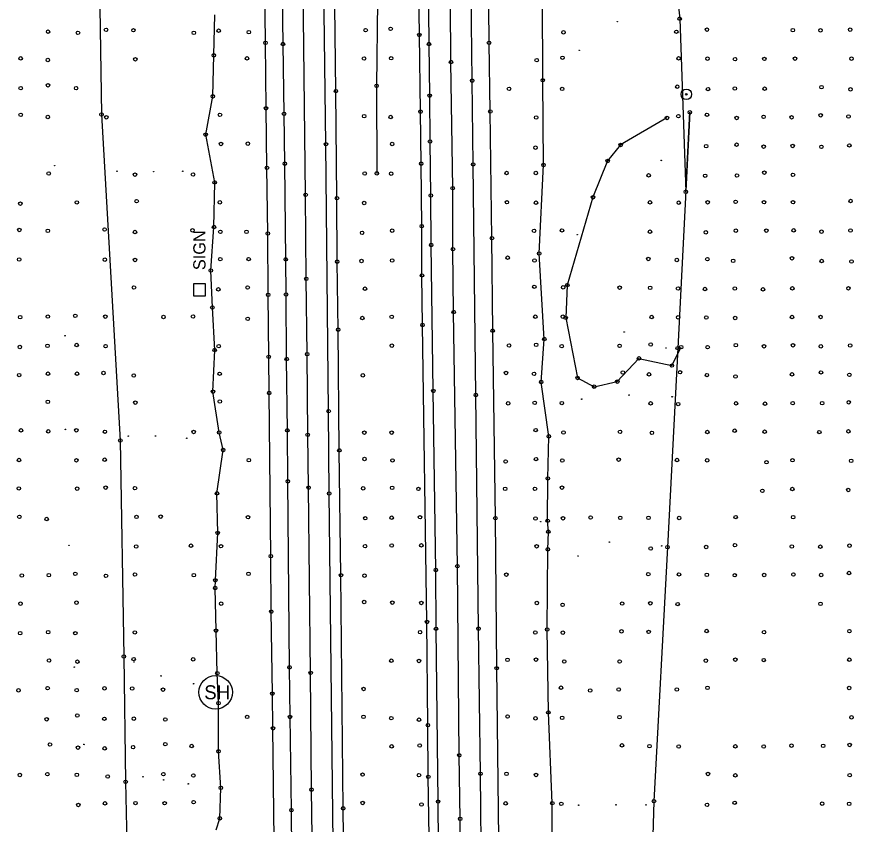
# Model space of a CAD drawing. Extents: x 20503438 to 20508873, y 7964251 to 7984667.
# Drawn here: x 20505218.6 to 20505698, y 7982806.9 to 7983269.7 of the extents above; entities that cross this region are included whole.
import ezdxf

# ---------------------------------------------------------------- set-up
doc = ezdxf.new("R2010")
doc.units = 0
for name, color, linetype in [('SurBreakLine', 7, 'Continuous'), ('SurControl', 7, 'Continuous'), ('SurDrainageArrowDown', 7, 'Continuous'), ('SurDrainageArrowUp', 7, 'Continuous'), ('SurEdgeRoadPaved', 7, 'Continuous'), ('SurEdgeShoulderPaved', 7, 'Continuous'), ('SurFenceWire', 7, 'Continuous'), ('SurNaturalCells', 7, 'Continuous'), ('SurPointsNonDTM', 7, 'Continuous'), ('SurRoadPoints', 7, 'Continuous'), ('SurSurveyPoints', 7, 'Continuous'), ('SurTreeLineRight', 7, 'Continuous')]:
    doc.layers.add(name, color=color, linetype=linetype)

msp = doc.modelspace()

# ---------------------------------------------------------------- linework, layer by layer
at = {"layer": 'SurBreakLine'}
for points in [[(20505388.09, 7982786.72), (20505387.46, 7982826.69), (20505386.97, 7982893.61), (20505385.8, 7982999.79), (20505385.32, 7983030.07), (20505384.98, 7983076.27), (20505384.47, 7983119.49), (20505384.1, 7983167.57), (20505382.15, 7983337.32), (20505379.76, 7983573.99), (20505379.24, 7983609.63), (20505378.24, 7983709.76), (20505377.29, 7983778.59), (20505376.87, 7983823.71), (20505376.2, 7983914.92), (20505375.66, 7983955.45), (20505374.47, 7984054.03), (20505371.04, 7984409.5), (20505370.34, 7984465.16)], [(20505472.94, 7982774.42), (20505472.68, 7982809.97), (20505472.15, 7982846.38), (20505471.07, 7982954.8), (20505468.94, 7983100.42), (20505468.55, 7983136.44), (20505468.38, 7983171.42), (20505467.38, 7983243.73), (20505467.16, 7983277.76), (20505466.96, 7983298.39), (20505466.31, 7983351.76), (20505465.95, 7983385.57), (20505465.78, 7983423.2), (20505464.95, 7983485.18), (20505463.87, 7983574.98), (20505462.87, 7983680.32), (20505462, 7983754.37)]]:
    msp.add_lwpolyline(points, dxfattribs=at)
at = {"layer": 'SurControl'}
for centre in [(20505562.72, 7983266.82), (20505540.92, 7983250.41), (20505587.88, 7983187.29), (20505240.3, 7983184.28), (20505275.98, 7983181.13), (20505297.02, 7983180.89), (20505313.71, 7983181.13), (20505539.78, 7983144.77), (20505246.26, 7983086.81), (20505566.66, 7983089.01), (20505590.66, 7983079.85), (20505542.35, 7983050.5), (20505569.5, 7983052.8), (20505594.17, 7983051.87), (20505246.45, 7983033.15), (20505282.48, 7983029.34), (20505298.08, 7983029.41), (20505315.98, 7983028.13), (20505518.87, 7982980.3), (20505248.53, 7982966.75), (20505558.2, 7982968.59), (20505588.18, 7982966.41), (20505540.27, 7982960.65), (20505285.75, 7982899.87), (20505251.54, 7982896.94), (20505301.31, 7982891.9), (20505319.88, 7982887.38), (20505257.06, 7982852.63), (20505290.94, 7982834.09), (20505302.75, 7982832.29), (20505316.82, 7982830.05), (20505540.57, 7982817.81), (20505562.01, 7982818), (20505579.21, 7982817.97)]:
    msp.add_circle(centre, 0.15, dxfattribs=at)
at = {"layer": 'SurDrainageArrowDown'}
msp.add_lwpolyline([(20505332.76, 7982803.76), (20505334.91, 7982810.26), (20505335.55, 7982827.71), (20505334.17, 7982848.71), (20505334.18, 7982876.28), (20505333.51, 7982893.44), (20505332.77, 7982917.85), (20505332.28, 7982942.23), (20505332.37, 7982946.68), (20505333.74, 7982973.81), (20505333.28, 7982996.49), (20505336.88, 7983021.4), (20505334.57, 7983031.42), (20505331, 7983054.83), (20505332.02, 7983078.67), (20505330.68, 7983103.07), (20505329.78, 7983124.21), (20505331.56, 7983149.14), (20505332.02, 7983174.71), (20505326.84, 7983202.11), (20505330.95, 7983224.07), (20505331.52, 7983247.58), (20505332.03, 7983270.82)], dxfattribs=at)
at = {"layer": 'SurDrainageArrowUp'}
for points in [[(20505435.69, 7983412.57), (20505432.5, 7983412.27), (20505429.44, 7983411.43), (20505426.11, 7983408.1), (20505425.72, 7983400.28), (20505426.05, 7983374.69), (20505426.24, 7983351.03), (20505426.02, 7983326.08), (20505425.25, 7983278.5), (20505424.77, 7983230.05), (20505424.95, 7983179.92)], [(20505525.47, 7982791.21), (20505525.48, 7982818.97), (20505523.24, 7982870.97), (20505522.53, 7982918.48), (20505522.94, 7982964.39), (20505523.24, 7982974.53), (20505522.79, 7982980.81), (20505522.94, 7983005.08), (20505523.5, 7983029.16), (20505519.1, 7983060.32), (20505520.91, 7983084.94), (20505517.95, 7983133.99), (20505520.47, 7983184.73), (20505520.01, 7983233.27), (20505519.87, 7983280.64)]]:
    msp.add_lwpolyline(points, dxfattribs=at)
at = {"layer": 'SurEdgeRoadPaved'}
for points in [[(20505399.87, 7982796.43), (20505397.64, 7982996.42), (20505397.31, 7983043.62), (20505395.75, 7983196.59), (20505394.62, 7983287.56), (20505393.71, 7983393.22), (20505391.47, 7983583.96), (20505391.16, 7983613.2), (20505390.95, 7983649.19), (20505388.69, 7983846.62), (20505387.86, 7983937.63), (20505387.13, 7984000.04), (20505387.09, 7984002.85), (20505386.65, 7984030.88), (20505382.6, 7984465.04)], [(20505484.93, 7982775.73), (20505484.31, 7982835.82), (20505483.21, 7982919), (20505481.67, 7983052.88), (20505480.16, 7983185.03), (20505479.57, 7983233.06), (20505478.99, 7983282.65), (20505478.07, 7983364.47), (20505477.49, 7983427.45), (20505476.34, 7983527.07), (20505475.78, 7983595.33), (20505474.69, 7983687.27), (20505474.16, 7983745.86), (20505473.26, 7983818.48), (20505472.69, 7983886.02), (20505472.06, 7983927.63), (20505471.61, 7983985.32), (20505470.9, 7984047.39), (20505470.84, 7984053.12), (20505468.38, 7984286.35), (20505467.61, 7984344.39), (20505467.44, 7984376.12), (20505466.29, 7984465.77)], [(20505376.87, 7982720.03), (20505375.97, 7982814.93), (20505375.18, 7982868.35), (20505374.84, 7982896.8), (20505373.9, 7983003.41), (20505373.63, 7983032.61), (20505373.23, 7983073.5), (20505372.9, 7983110.52), (20505372.72, 7983130.62), (20505372.2, 7983185.46), (20505371.76, 7983214.03), (20505371.18, 7983254.01), (20505370.55, 7983308.55), (20505370.11, 7983376.99), (20505368.96, 7983469.33), (20505368.55, 7983508.46), (20505368.26, 7983546.26), (20505367.99, 7983574.82), (20505367.67, 7983598.7), (20505367.02, 7983649.08), (20505365.92, 7983751.56)], [(20505460.57, 7982745.92), (20505460.02, 7982819.87), (20505458.85, 7982918.92), (20505458.72, 7982952.55), (20505457.28, 7983055.18), (20505456.07, 7983138.84), (20505455.85, 7983167.22), (20505455.42, 7983198.13), (20505455.22, 7983224.45), (20505454.85, 7983254.02), (20505454.55, 7983292.83), (20505453.72, 7983358.98), (20505453.59, 7983387.67), (20505452.51, 7983492.09), (20505451.03, 7983612.62), (20505450.51, 7983669.13), (20505449.78, 7983725.38), (20505449.64, 7983752.99)]]:
    msp.add_lwpolyline(points, dxfattribs=at)
at = {"layer": 'SurEdgeShoulderPaved'}
for points in [[(20505495.09, 7982782.36), (20505493.62, 7982896.29), (20505492.84, 7982982.27), (20505491.34, 7983089.74), (20505490.88, 7983142.78), (20505489.93, 7983215.38), (20505489.23, 7983254.71), (20505488.8, 7983316.65), (20505488.28, 7983347.9), (20505487.72, 7983412.22), (20505487.68, 7983415.04), (20505486.79, 7983497.7), (20505486.21, 7983568.02), (20505484.96, 7983655.65), (20505482.47, 7983897.96)], [(20505406.44, 7982753), (20505405.66, 7982815.99), (20505404.36, 7982949.58), (20505403.42, 7983021.17), (20505402.75, 7983090.32), (20505402.21, 7983129.29), (20505402.08, 7983165.66), (20505401.47, 7983227.06), (20505400.04, 7983341.4), (20505399.38, 7983413.75), (20505397.66, 7983569.46), (20505397.07, 7983624.87), (20505396.26, 7983698.73), (20505395.49, 7983760.73)], [(20505366.98, 7982718.13), (20505365.41, 7982861.87), (20505365.07, 7982881.72), (20505364.41, 7982928.72), (20505364.19, 7982960.53), (20505363.22, 7983054.03), (20505362.96, 7983074.76), (20505362.61, 7983110.31), (20505362.42, 7983145.46), (20505361.97, 7983183.06), (20505361.41, 7983217.22), (20505361.15, 7983254.72), (20505360.71, 7983288.06), (20505360.6, 7983299.77), (20505360.47, 7983317.66), (20505360.11, 7983363.4), (20505359.23, 7983433.57), (20505358.71, 7983478.18), (20505357.37, 7983616.7), (20505356.33, 7983687.67), (20505355.63, 7983757.41)], [(20505454.87, 7982799.91), (20505454.43, 7982834.05), (20505454.19, 7982863.65), (20505453.63, 7982922.83), (20505451.09, 7983092.97), (20505450.78, 7983121.42), (20505450.67, 7983149.63), (20505450.35, 7983185.44), (20505449.91, 7983215.31), (20505449.29, 7983259.23), (20505449.04, 7983285.01), (20505448.83, 7983321.6), (20505448.42, 7983357.03), (20505448.19, 7983377.57), (20505447.91, 7983416.56), (20505446.96, 7983486.61), (20505445.72, 7983599.24), (20505445.42, 7983622.54), (20505445.14, 7983645.21), (20505445.01, 7983677.11), (20505444.05, 7983741.95)]]:
    msp.add_lwpolyline(points, dxfattribs=at)
at = {"layer": 'SurFenceWire'}
for points in [[(20505559.43, 7984640.78), (20505560.17, 7984588.37), (20505562.54, 7984378.42), (20505563.28, 7984280.23), (20505565.01, 7984077.63), (20505567.76, 7983869.69), (20505568.29, 7983819.98), (20505570.2, 7983612.37), (20505577.97, 7983452.36), (20505588.36, 7983359.69), (20505598.48, 7983268.53), (20505602.02, 7983169.29), (20505604.28, 7983214.9), (20505597.36, 7983079.77), (20505591.48, 7982965.7), (20505583.74, 7982820.12), (20505580.19, 7982701.02)], [(20505263.07, 7983570.84), (20505264.2, 7983465.89), (20505264.6, 7983384.22), (20505265.76, 7983299.57), (20505267.13, 7983213.61), (20505277.91, 7983026.79), (20505279.9, 7982903.03), (20505280.94, 7982831.19), (20505284.45, 7982664.16), (20505302.4, 7982645.24), (20505317.11, 7982628.42), (20505340.63, 7982610.34)]]:
    msp.add_lwpolyline(points, dxfattribs=at)
at = {"layer": 'SurNaturalCells'}
msp.add_circle((20505332.54, 7982882.51), 9.59, dxfattribs=at)
at = {"layer": 'SurPointsNonDTM'}
for centre in [(20505598.48, 7983268.53), (20505267.13, 7983213.61), (20505591.19, 7983211.65), (20505604.28, 7983214.9), (20505564.63, 7983196.17), (20505557.18, 7983187.03), (20505602.02, 7983169.29), (20505548.76, 7983166.18), (20505534.06, 7983115.88), (20505533.17, 7983097.07), (20505597.36, 7983079.77), (20505599.33, 7983080.32), (20505575.13, 7983073.88), (20505594.02, 7983069.75), (20505539.96, 7983062.66), (20505549.45, 7983057.65), (20505562.73, 7983060.56), (20505277.91, 7983026.79), (20505591.48, 7982965.7), (20505279.9, 7982903.03), (20505280.94, 7982831.19), (20505583.74, 7982820.12)]:
    msp.add_circle(centre, 1, dxfattribs=at)
at = {"layer": 'SurRoadPoints'}
msp.add_lwpolyline([(20505326.66, 7983113.23), (20505326.66, 7983113.23), (20505326.66, 7983116.66), (20505319.8, 7983116.66), (20505319.8, 7983109.8), (20505326.66, 7983109.8), (20505326.66, 7983113.23)], dxfattribs=at)
for radius in [3, 0.5]:
    msp.add_circle((20505602.28, 7983225.21), radius, dxfattribs=at)
at = {"layer": 'SurSurveyPoints'}
for centre in [(20505236.52, 7983261.11), (20505253.65, 7983260.41), (20505269.75, 7983262.13), (20505285.42, 7983261.93), (20505320.03, 7983260.48), (20505334.27, 7983261.65), (20505351.53, 7983260.86), (20505418.48, 7983261.99), (20505432.81, 7983262.76), (20505449.29, 7983259.23), (20505531.93, 7983260.73), (20505596.56, 7983261.06), (20505614.08, 7983262.29), (20505663.32, 7983262.01), (20505679.16, 7983261.88), (20505696.22, 7983262.28), (20505361.15, 7983254.72), (20505371.18, 7983254.01), (20505454.85, 7983254.02), (20505489.23, 7983254.71), (20505220.82, 7983245.81), (20505236.4, 7983244.85), (20505286.54, 7983245.3), (20505331.52, 7983247.58), (20505350.47, 7983245.83), (20505417.57, 7983245.74), (20505433.15, 7983245.88), (20505516.53, 7983244.78), (20505531.29, 7983246.16), (20505597.86, 7983245.81), (20505614.4, 7983245.63), (20505630.19, 7983245.37), (20505647.01, 7983245.5), (20505664.53, 7983245.68), (20505696.96, 7983245.64), (20505467.38, 7983243.73), (20505236.49, 7983230.38), (20505424.77, 7983230.05), (20505479.57, 7983233.06), (20505520.01, 7983233.27), (20505597.08, 7983229.55), (20505220.85, 7983228.72), (20505252.57, 7983228.7), (20505401.47, 7983227.06), (20505500.68, 7983228.33), (20505531.14, 7983228.31), (20505614.72, 7983228.21), (20505630.12, 7983228.55), (20505647.17, 7983228.44), (20505679.77, 7983229.27), (20505696.37, 7983228.08), (20505330.95, 7983224.07), (20505455.22, 7983224.45), (20505361.41, 7983217.22), (20505449.91, 7983215.31), (20505489.93, 7983215.38), (20505220.82, 7983213.48), (20505236.35, 7983212.18), (20505269.9, 7983212.06), (20505335.01, 7983213.48), (20505371.76, 7983214.03), (20505417.67, 7983212.71), (20505432.87, 7983212.18), (20505516.21, 7983211.89), (20505597.71, 7983212.68), (20505614.12, 7983213.5), (20505631.1, 7983211.66), (20505646.56, 7983212.29), (20505662.61, 7983212.05), (20505679.32, 7983213.2), (20505695.23, 7983212.51), (20505326.84, 7983202.11), (20505335.62, 7983196.74), (20505351.03, 7983196.97), (20505395.75, 7983196.59), (20505433.74, 7983196.73), (20505455.42, 7983198.13), (20505631.09, 7983196.33), (20505695.73, 7983195.92), (20505515.85, 7983194.63), (20505613.64, 7983195.48), (20505646.58, 7983195.21), (20505663.24, 7983195.62), (20505679.71, 7983195.1), (20505361.97, 7983183.06), (20505372.2, 7983185.46), (20505450.35, 7983185.44), (20505480.16, 7983185.03), (20505520.47, 7983184.73), (20505236.86, 7983179.83), (20505286.37, 7983179.18), (20505319.57, 7983179.22), (20505417.96, 7983179.86), (20505424.95, 7983179.92), (20505433.17, 7983179.7), (20505499.28, 7983180.08), (20505516.06, 7983180.09), (20505580.7, 7983178.77), (20505613.09, 7983178.53), (20505631.3, 7983178.7), (20505647.03, 7983180.32), (20505663.38, 7983179.03), (20505332.02, 7983174.71), (20505384.1, 7983167.57), (20505455.85, 7983167.22), (20505468.38, 7983171.42), (20505220.63, 7983162.55), (20505253.01, 7983163.25), (20505287.28, 7983164), (20505334.96, 7983163.28), (20505402.08, 7983165.66), (20505417.69, 7983162.95), (20505499.47, 7983163.36), (20505516.14, 7983163.07), (20505581.48, 7983163.29), (20505597.95, 7983163.07), (20505614.5, 7983163.32), (20505630.54, 7983163.61), (20505646.84, 7983163.35), (20505663.44, 7983163.36), (20505696.42, 7983164.05), (20505331.56, 7983149.14), (20505450.67, 7983149.63), (20505220.03, 7983147.45), (20505236.39, 7983146.97), (20505268.92, 7983147.72), (20505286.35, 7983146.28), (20505319.25, 7983147.26), (20505335.24, 7983146.36), (20505350.26, 7983146.39), (20505362.42, 7983145.46), (20505416.47, 7983145.82), (20505433.69, 7983147.03), (20505515.03, 7983146.96), (20505531.01, 7983147.21), (20505581.5, 7983146.46), (20505613.49, 7983146.13), (20505630.67, 7983147.05), (20505648.12, 7983147.07), (20505663.84, 7983147.22), (20505679.72, 7983146.51), (20505696.34, 7983147.14), (20505456.07, 7983138.84), (20505490.88, 7983142.78), (20505468.55, 7983136.44), (20505517.95, 7983133.99), (20505219.92, 7983130.55), (20505269.03, 7983130.43), (20505286.29, 7983130.28), (20505335.2, 7983130.71), (20505351.43, 7983130.78), (20505372.72, 7983130.62), (20505402.21, 7983129.29), (20505416.11, 7983129.69), (20505433.67, 7983129.95), (20505499.86, 7983131.59), (20505515.31, 7983130), (20505580.47, 7983130.85), (20505596.82, 7983130.21), (20505614.34, 7983130.77), (20505629.11, 7983129.78), (20505662.85, 7983131.24), (20505679.83, 7983129.67), (20505696.94, 7983129.4), (20505329.78, 7983124.21), (20505384.47, 7983119.49), (20505450.78, 7983121.42), (20505285.73, 7983114.46), (20505350.86, 7983114.5), (20505515.17, 7983114.92), (20505531.74, 7983114.55), (20505564.07, 7983114.43), (20505334.11, 7983113.42), (20505362.61, 7983110.31), (20505372.9, 7983110.52), (20505418.14, 7983113.8), (20505581.55, 7983114.33), (20505597.54, 7983113.93), (20505613.02, 7983113.6), (20505630.09, 7983113.91), (20505646.25, 7983113.41), (20505663.08, 7983113.99), (20505695.18, 7983114.05), (20505330.68, 7983103.07), (20505468.94, 7983100.42), (20505220.52, 7983097.49), (20505236.35, 7983097.83), (20505252.13, 7983098.26), (20505269.31, 7983097.81), (20505302.66, 7983097.56), (20505319.57, 7983097.9), (20505350.94, 7983096.55), (20505416.65, 7983097), (20505433.46, 7983097.65), (20505515.75, 7983097.74), (20505531.49, 7983097.82), (20505582.43, 7983097.58), (20505597.59, 7983097.4), (20505613.71, 7983097.29), (20505630.28, 7983097.04), (20505662.82, 7983097.55), (20505679.23, 7983097.62), (20505451.09, 7983092.97), (20505402.75, 7983090.32), (20505491.34, 7983089.74), (20505236.16, 7983081.09), (20505252.93, 7983081.53), (20505269.47, 7983080.89), (20505334.3, 7983080.88), (20505433.52, 7983081.18), (20505500.67, 7983081.27), (20505516.27, 7983081.61), (20505520.91, 7983084.94), (20505530.89, 7983080.9), (20505564.03, 7983081.09), (20505581.89, 7983081.79), (20505630.63, 7983081.48), (20505663.45, 7983081.36), (20505696.15, 7983081.23), (20505220.3, 7983080.4), (20505332.02, 7983078.67), (20505384.98, 7983076.27), (20505614.5, 7983080.28), (20505646.78, 7983080.82), (20505679.36, 7983080.77), (20505362.96, 7983074.76), (20505373.23, 7983073.5), (20505219.94, 7983064.3), (20505236.51, 7983065.11), (20505253.05, 7983065.1), (20505268.26, 7983065.45), (20505285.61, 7983064.08), (20505334.84, 7983065.06), (20505416.86, 7983064.12), (20505498.9, 7983065.53), (20505515.02, 7983065.04), (20505565.92, 7983065.81), (20505580.88, 7983064.72), (20505598.71, 7983065.93), (20505614.08, 7983064.3), (20505630.48, 7983063.5), (20505662.84, 7983064.7), (20505679.43, 7983065.82), (20505695.71, 7983064.48), (20505519.1, 7983060.32), (20505331, 7983054.83), (20505363.22, 7983054.03), (20505457.28, 7983055.18), (20505481.67, 7983052.88), (20505236.41, 7983048.97), (20505286.52, 7983048.5), (20505334.95, 7983049.16), (20505500.18, 7983048.07), (20505515.4, 7983048.38), (20505530.97, 7983048.25), (20505581.83, 7983048.1), (20505597.62, 7983047.68), (20505630.81, 7983048.1), (20505647.36, 7983047.9), (20505663.24, 7983048.23), (20505680.1, 7983048.24), (20505695.37, 7983048.69), (20505397.31, 7983043.62), (20505220.99, 7983032.63), (20505236.61, 7983032.04), (20505252.69, 7983032.67), (20505269.08, 7983031.82), (20505319.95, 7983031.69), (20505334.57, 7983031.42), (20505373.63, 7983032.61), (20505385.32, 7983030.07), (20505417.8, 7983031.3), (20505433.45, 7983031.32), (20505515.95, 7983032.77), (20505523.5, 7983029.16), (20505531.87, 7983031.4), (20505564.28, 7983031.79), (20505582.56, 7983031.19), (20505614.37, 7983031.66), (20505630, 7983032.4), (20505647.15, 7983031.87), (20505678.51, 7983031.63), (20505695.18, 7983032.03), (20505336.88, 7983021.4), (20505403.42, 7983021.17), (20505219.84, 7983015.6), (20505252.76, 7983015.46), (20505268.95, 7983015.8), (20505351.59, 7983015.54), (20505417.88, 7983016.17), (20505433.89, 7983015.39), (20505498.71, 7983014.8), (20505516.18, 7983016.15), (20505531.2, 7983015.37), (20505563.48, 7983015.86), (20505596.94, 7983015.62), (20505614.25, 7983015.43), (20505648.27, 7983014.35), (20505663.13, 7983015.49), (20505696.73, 7983015.14), (20505522.94, 7983005.08), (20505269.56, 7982999.79), (20505286.3, 7982999.46), (20505373.9, 7983003.41), (20505385.8, 7982999.79), (20505433.68, 7982999.68), (20505531.04, 7982999.79), (20505219.75, 7982999.34), (20505253.22, 7982999.23), (20505333.28, 7982996.49), (20505397.64, 7982996.42), (20505417.08, 7982999.36), (20505448.75, 7982999.06), (20505498.5, 7982999.08), (20505515.53, 7982999.11), (20505645.87, 7982997.97), (20505663.06, 7982998.98), (20505695.08, 7982998.46), (20505220.05, 7982983.05), (20505235.74, 7982981.81), (20505287.19, 7982983.01), (20505301.04, 7982983.17), (20505351.09, 7982982.83), (20505418.28, 7982982.25), (20505433.46, 7982982.55), (20505449.68, 7982982.83), (20505492.84, 7982982.27), (20505515.88, 7982982.12), (20505522.79, 7982980.81), (20505531.61, 7982982.24), (20505547.44, 7982982.68), (20505564.42, 7982982.45), (20505580.62, 7982982.49), (20505598.2, 7982982.37), (20505630.6, 7982982.91), (20505663.5, 7982982.88), (20505333.74, 7982973.81), (20505523.24, 7982974.53), (20505286.96, 7982966.04), (20505318.46, 7982966.51), (20505335.6, 7982966.2), (20505418.16, 7982966.24), (20505433.45, 7982966.64), (20505450.46, 7982966.7), (20505516.51, 7982966.16), (20505613.65, 7982965.81), (20505630.15, 7982966.84), (20505662.77, 7982966.02), (20505679.1, 7982965.96), (20505695.8, 7982966.57), (20505522.94, 7982964.39), (20505581.89, 7982964.92), (20505364.19, 7982960.53), (20505458.72, 7982952.55), (20505471.07, 7982954.8), (20505221.49, 7982949.4), (20505236.91, 7982949.64), (20505252.1, 7982950.36), (20505269.69, 7982949.26), (20505286.3, 7982949.99), (20505320.06, 7982949.65), (20505332.37, 7982946.68), (20505351.41, 7982950.36), (20505404.36, 7982949.58), (20505417.88, 7982949.33), (20505499.17, 7982949.95), (20505580.48, 7982950.2), (20505598.06, 7982950.06), (20505614.03, 7982949.85), (20505630.04, 7982949.58), (20505646.92, 7982949.75), (20505663.66, 7982950.03), (20505679.53, 7982949.7), (20505695.5, 7982950.85), (20505332.28, 7982942.23), (20505220.69, 7982933.33), (20505252.8, 7982933.88), (20505335.71, 7982933.29), (20505417.64, 7982934.29), (20505433.78, 7982933.87), (20505450.45, 7982933.72), (20505516.59, 7982933.72), (20505531.37, 7982932.62), (20505565.52, 7982933.34), (20505581.65, 7982933.52), (20505597.35, 7982933.05), (20505679.15, 7982933.19), (20505364.41, 7982928.72), (20505453.63, 7982922.83), (20505458.85, 7982918.92), (20505483.21, 7982919), (20505522.53, 7982918.48), (20505220.51, 7982916.37), (20505236.58, 7982916.96), (20505252.12, 7982916.34), (20505286.26, 7982916.82), (20505332.77, 7982917.85), (20505449.71, 7982916.98), (20505515.73, 7982916.79), (20505531.52, 7982916.68), (20505565.11, 7982917.45), (20505580.67, 7982917.11), (20505613.95, 7982917.63), (20505646.82, 7982916.93), (20505695.75, 7982917.5), (20505237.07, 7982900.76), (20505253.33, 7982900.02), (20505285.58, 7982901.53), (20505319.67, 7982901.37), (20505433.2, 7982900.61), (20505449.13, 7982900.45), (20505499.82, 7982901.09), (20505516.16, 7982901.23), (20505532.32, 7982900.18), (20505564.08, 7982900.15), (20505613.49, 7982900.67), (20505630.41, 7982901.21), (20505646.66, 7982900.96), (20505695.7, 7982901.17), (20505374.84, 7982896.8), (20505493.62, 7982896.29), (20505333.51, 7982893.44), (20505386.97, 7982893.61), (20505236.26, 7982884.83), (20505268.87, 7982884.75), (20505284.74, 7982884.7), (20505417.32, 7982884.41), (20505530.46, 7982885.12), (20505614.4, 7982885.08), (20505695.64, 7982885), (20505219.55, 7982883.6), (20505252.9, 7982883.74), (20505302.37, 7982884.05), (20505365.07, 7982881.72), (20505547.19, 7982883.54), (20505563.52, 7982884.08), (20505596.83, 7982884.1), (20505334.18, 7982876.28), (20505523.24, 7982870.97), (20505235.75, 7982867.02), (20505253.26, 7982869.18), (20505268.78, 7982867.34), (20505285.65, 7982867.38), (20505303.69, 7982866.88), (20505350.63, 7982868.39), (20505375.18, 7982868.35), (20505417.31, 7982868.45), (20505433.19, 7982867.67), (20505449.07, 7982866.79), (20505499.85, 7982868.62), (20505515.86, 7982867.54), (20505531.15, 7982867.86), (20505564.02, 7982868.25), (20505696.95, 7982868.13), (20505365.41, 7982861.87), (20505454.19, 7982863.65), (20505237.61, 7982852.58), (20505253.69, 7982850.78), (20505285.23, 7982851.03), (20505303.71, 7982852.79), (20505318.84, 7982851.68), (20505433.46, 7982851.52), (20505449.48, 7982851.99), (20505565.43, 7982852.06), (20505581.17, 7982851.59), (20505597.92, 7982851.45), (20505630.4, 7982851.52), (20505646.65, 7982851.42), (20505662.54, 7982851.89), (20505680.72, 7982851.79), (20505695.92, 7982852.33), (20505268.99, 7982850.38), (20505334.17, 7982848.71), (20505472.15, 7982846.38), (20505220.34, 7982835.12), (20505236.13, 7982835.57), (20505253.03, 7982835.18), (20505270.68, 7982834.25), (20505302.58, 7982835.59), (20505319.78, 7982834.82), (20505416.75, 7982835.35), (20505449.07, 7982835), (20505454.43, 7982834.05), (20505484.31, 7982835.82), (20505499.23, 7982835.76), (20505516.11, 7982835.14), (20505614.75, 7982835.71), (20505630.39, 7982834.87), (20505695.93, 7982835.01), (20505335.55, 7982827.71), (20505387.46, 7982826.69), (20505253.88, 7982817.91), (20505269.18, 7982818.82), (20505286.61, 7982819.01), (20505303.31, 7982818.92), (20505319.94, 7982819.57), (20505416.82, 7982819.06), (20505450.52, 7982818.18), (20505460.02, 7982819.87), (20505498.77, 7982818.84), (20505525.48, 7982818.97), (20505530.63, 7982818.59), (20505614.16, 7982818.02), (20505629.99, 7982819.2), (20505680.16, 7982818.66), (20505695.61, 7982818.58), (20505375.97, 7982814.93), (20505405.66, 7982815.99), (20505334.91, 7982810.26), (20505472.68, 7982809.97)]:
    msp.add_circle(centre, 1, dxfattribs=at)
at = {"layer": 'SurTreeLineRight'}
msp.add_lwpolyline([(20505591.19, 7983211.65), (20505564.63, 7983196.17), (20505557.18, 7983187.03), (20505548.76, 7983166.18), (20505534.06, 7983115.88), (20505533.17, 7983097.07), (20505539.96, 7983062.66), (20505549.45, 7983057.65), (20505562.73, 7983060.56), (20505575.13, 7983073.88), (20505594.02, 7983069.75), (20505599.33, 7983080.32)], dxfattribs=at)

# ---------------------------------------------------------------- texts
at = {"layer": 'SurNaturalCells'}
msp.add_text('SH', height=7.995, rotation=360, dxfattribs=at).set_placement((20505326.02, 7982878.51))
at = {"layer": 'SurRoadPoints'}
msp.add_text('SIGN', height=6.995, rotation=90, dxfattribs=at).set_placement((20505326.73, 7983124.44))

doc.saveas('drawing.dxf')
